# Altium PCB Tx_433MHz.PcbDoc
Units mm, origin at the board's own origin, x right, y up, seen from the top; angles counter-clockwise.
Board outline 100 x 50 mm, 4 copper layers (SIGNAL_1, SIGNAL_2, SIGNAL_3, SIGNAL_4), stack 1.58 mm thick; 34 components, 85 nets, 122 pads, 0 vias.
Unrouted connection lines stored in the file: 89.
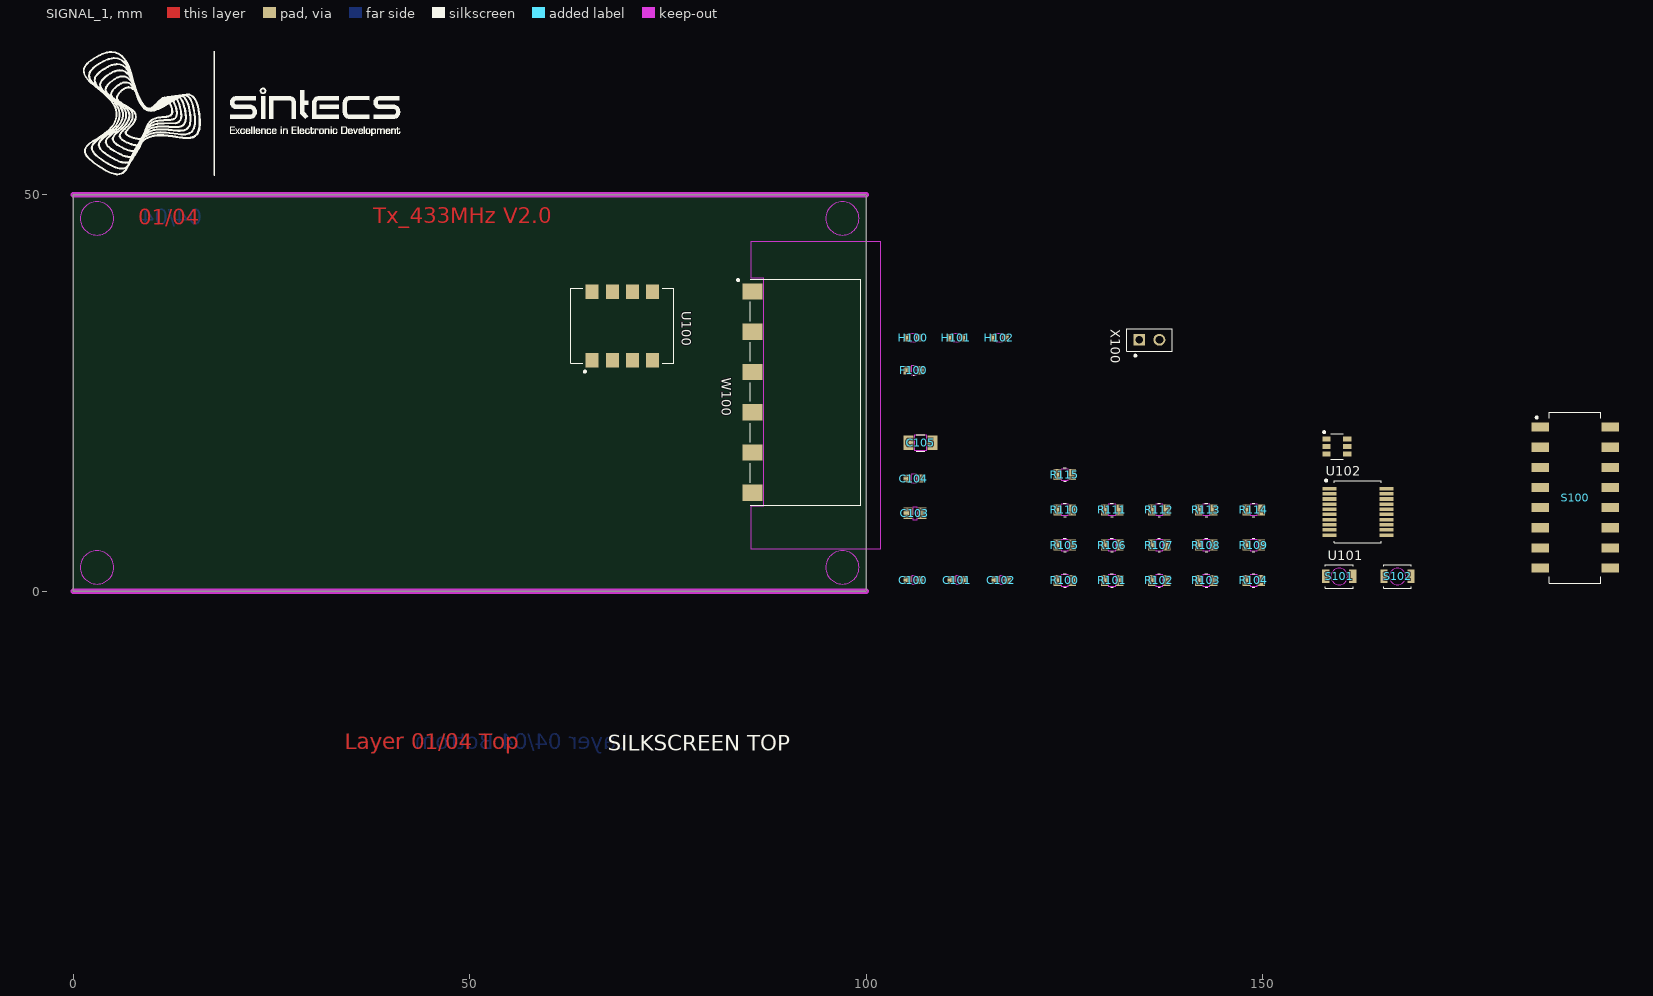
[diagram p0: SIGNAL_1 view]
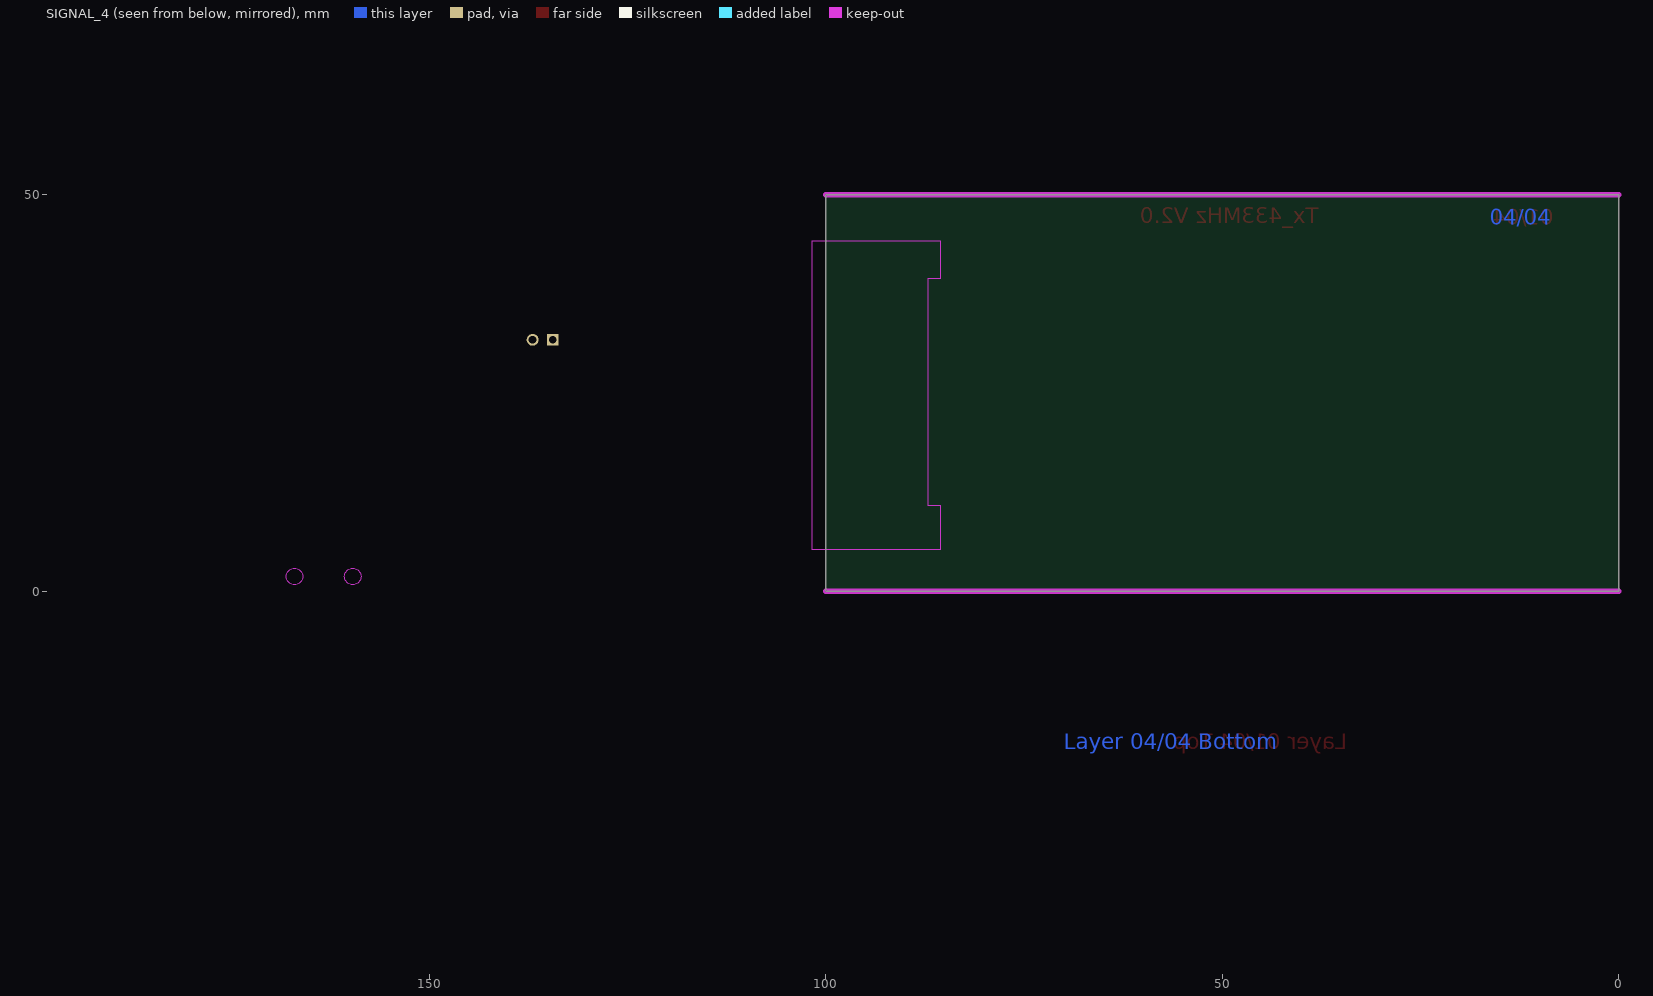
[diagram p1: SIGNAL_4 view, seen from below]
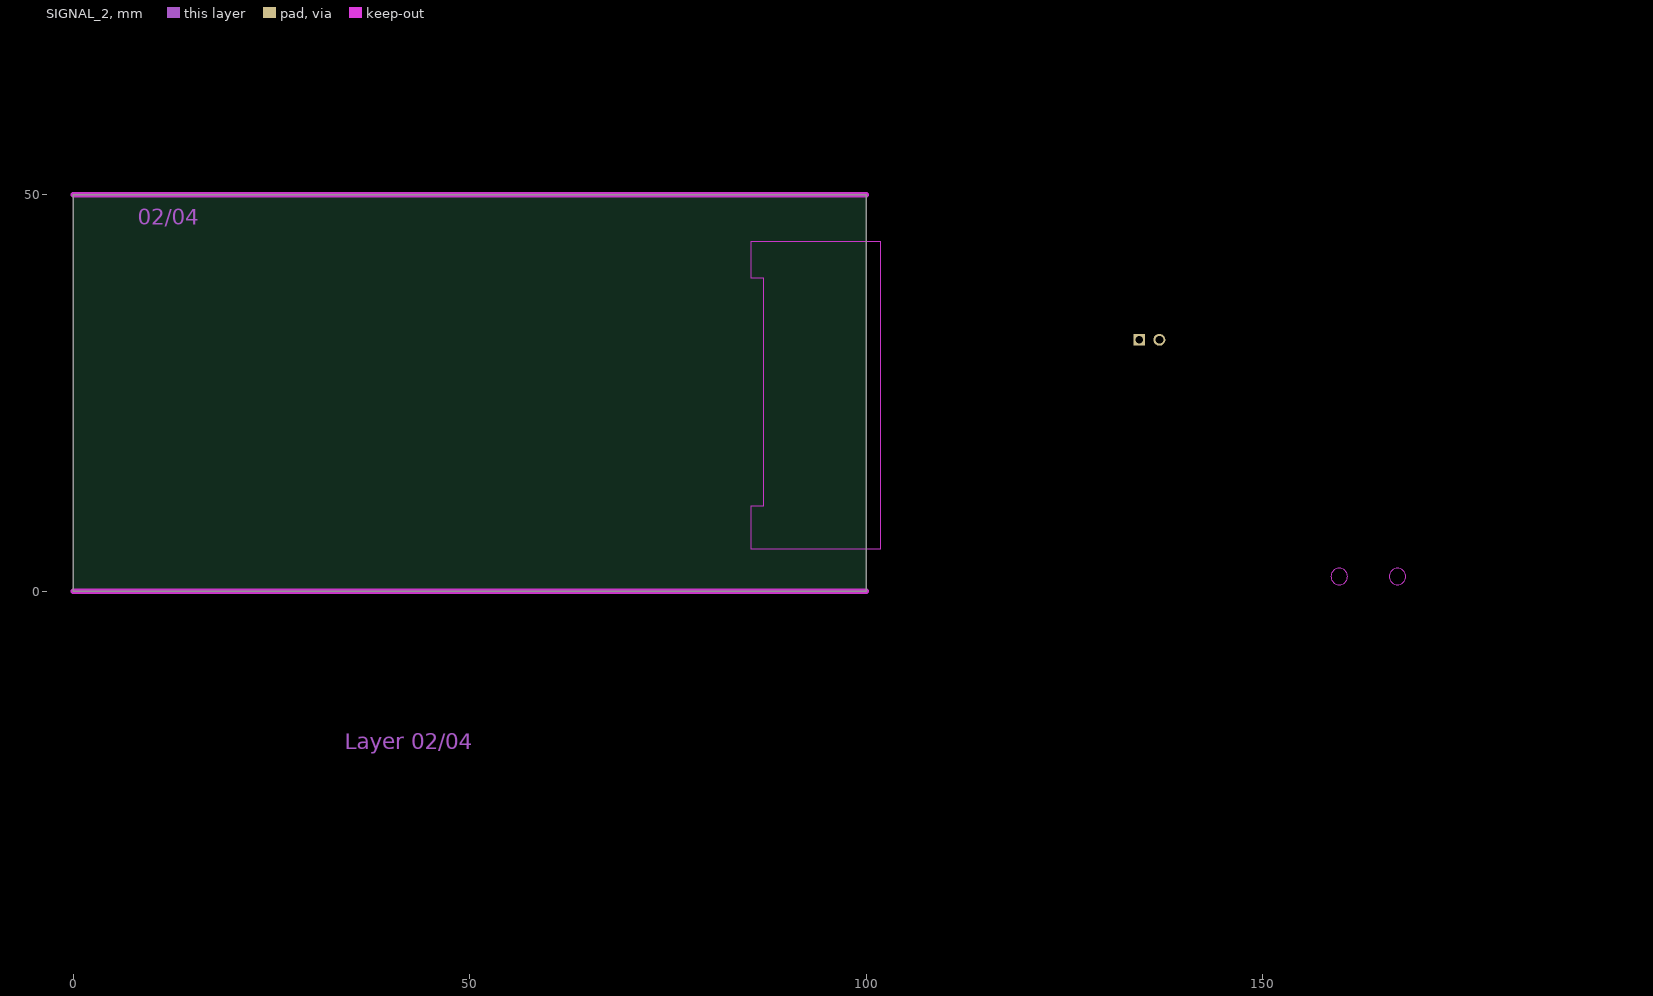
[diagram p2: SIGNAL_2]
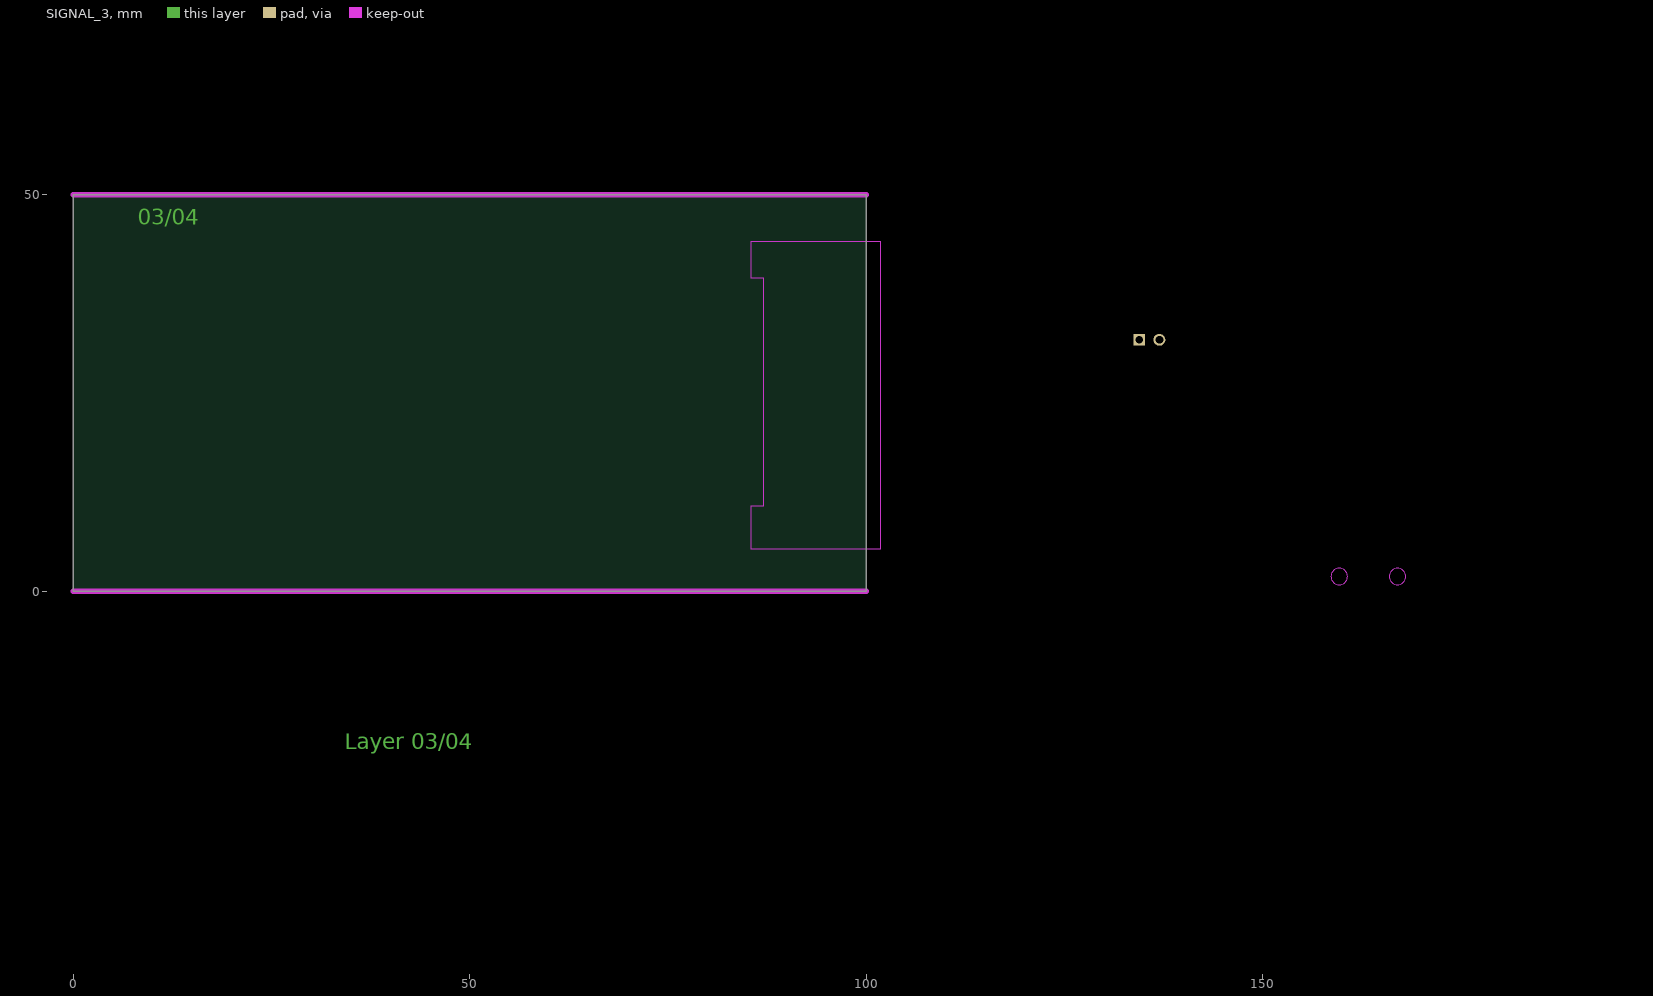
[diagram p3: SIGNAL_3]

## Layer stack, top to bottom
DIELECTRIC_1: solder mask 0.01, Dk 1
SIGNAL_1: signal copper 0.035
DIELECTRIC_3: prepreg 0.12, Dk 4.7
SIGNAL_2: signal copper 0.035
DIELECTRIC_5: prepreg 1.2, Dk 4.7
SIGNAL_3: signal copper 0.035
DIELECTRIC_7: prepreg 0.12, Dk 4.7
SIGNAL_4: signal copper 0.035
DIELECTRIC_9: solder mask 0.01, Dk 1

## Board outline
0,0 100,0 100,50 0,50

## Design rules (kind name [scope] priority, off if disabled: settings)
Clearance [All] p1: gap=0.15 ignorepadtopadclearanceinfootprint=FALSE
ComponentClearance [All] p1: gap=0.1 collisioncheckmode=3 verticalgap=0.254 showdistances=FALSE
DiffPairsRouting [All] p1: maxlimit=0.254 minlimit=0.254 mostfreqgap=0.254 toplayer_minwidth=0.15 toplayer_maxwidth=0.3 toplayer_prefwidth=0.15 midlayer1_minwidth=0.15 midlayer1_maxwidth=0.3 midlayer1_prefwidth=0.15 midlayer2_minwidth=0.15 midlayer2_maxwidth=0.3 midlayer2_prefwidth=0.15 bottomlayer_minwidth=0.15 bottomlayer_maxwidth=0.3 bottomlayer_prefwidth=0.15 maxuncoupledlength=12.7
PolygonConnect [All] p1: thpad.connectstyle=Relief thpad.reliefconductorwidth=0.15 thpad.reliefentries=4 thpad.polygonreliefangle="90 Angle" thpad.airgapwidth=0.15 smdpad.connectstyle=Relief smdpad.reliefconductorwidth=0.15 smdpad.reliefentries=4 smdpad.polygonreliefangle="90 Angle" smdpad.airgapwidth=0.15 via.connectstyle=Direct via.reliefconductorwidth=0.127 via.reliefentries=2 via.polygonreliefangle="90 Angle" via.airgapwidth=0.152
RoutingVias [All] p1: holewidth=0.3 width=0.7 viastyle="Through Hole" minholewidth=0.3 minwidth=0.7 maxholewidth=0.3 maxwidth=0.7
SolderMaskExpansion SolderMaskExpansion_Via [IsVia] p1: expansion=0.075 istentingtop=FALSE soldermaskfromhole=TRUE
SolderMaskExpansion [All] p2: expansion=0.1 istentingtop=FALSE
SupplyNets "Schematic Supply Nets_1" [InNet('3V3_TX')] p1: voltage=0.000
SupplyNets "Schematic Supply Nets" [InNet('GND_TX')] p2: voltage=0.000
UnRoutedNet [All] p1: checkbadconnections=TRUE
Width "Width for 50E_SE" [InNetClass('50R')] p1: maxlimit=0.2 minlimit=0.185 preferedwidth=0.2 toplayer_minwidth=0.2 bottomlayer_minwidth=0.2 impedanceprofiledriven=TRUE minimp=50.000000 maximp=50.000000 favimp=50.000000
Width [All] p2: maxlimit=1 minlimit=0.15 preferedwidth=0.2
27 further rules are at their usual default settings.

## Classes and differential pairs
net class 50R: $1N1841_TX

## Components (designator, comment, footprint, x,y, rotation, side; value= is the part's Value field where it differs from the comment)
C100 "C_0603_1608X90_GENERIC" CAPC1608X90N_0603_GENERIC 105.95,1.4 r0 top
C101 "C_0603_1608X90_GENERIC" CAPC1608X90N_0603_GENERIC 111.5,1.4 r0 top
C102 "C_0603_1608X90_GENERIC" CAPC1608X90N_0603_GENERIC 117.05,1.4 r0 top
C103 "C_0805_2012X150_GENERIC" CAPC2012X150N_0805_GENERIC 106.15,9.8 r0 top
C104 "CL10A226MP8NUNE" CAPC1608X105N 106,14.2 r0 top
C105 "C_1206_3216X190_GENERIC" CAPC3216X190N_1206_GENERIC 106.85,18.7 r0 top
F100 "0467XXXX" RESC1608X60N_0603_GENERIC 106,27.85 r0 top
H100 "KP-1608SGC" LEDC1608X110N 105.9,31.95 r0 top
H101 "KP-1608SGC" LEDC1608X110N 111.35,31.95 r0 top
H102 "KP-1608SGC" LEDC1608X110N 116.8,31.95 r0 top
R100 "R_0805_2012X60_GENERIC" RESC2012X60N_0805_GENERIC 125.05,1.35 r0 top
R101 "R_0805_2012X60_GENERIC" RESC2012X60N_0805_GENERIC 131,1.35 r0 top
R102 "R_0805_2012X60_GENERIC" RESC2012X60N_0805_GENERIC 136.95,1.35 r0 top
R103 "R_0805_2012X60_GENERIC" RESC2012X60N_0805_GENERIC 142.9,1.35 r0 top
R104 "R_0805_2012X60_GENERIC" RESC2012X60N_0805_GENERIC 148.85,1.35 r0 top
R105 "R_0805_2012X60_GENERIC" RESC2012X60N_0805_GENERIC 125.05,5.8 r0 top
R106 "R_0805_2012X60_GENERIC" RESC2012X60N_0805_GENERIC 131,5.8 r0 top
R107 "R_0805_2012X60_GENERIC" RESC2012X60N_0805_GENERIC 136.95,5.8 r0 top
R108 "R_0805_2012X60_GENERIC" RESC2012X60N_0805_GENERIC 142.9,5.8 r0 top
R109 "R_0805_2012X60_GENERIC" RESC2012X60N_0805_GENERIC 148.85,5.8 r0 top
R110 "R_0805_2012X60_GENERIC" RESC2012X60N_0805_GENERIC 125.05,10.25 r0 top
R111 "R_0805_2012X60_GENERIC" RESC2012X60N_0805_GENERIC 131,10.25 r0 top
R112 "R_0805_2012X60_GENERIC" RESC2012X60N_0805_GENERIC 136.95,10.25 r0 top
R113 "R_0805_2012X60_GENERIC" RESC2012X60N_0805_GENERIC 142.9,10.25 r0 top
R114 "R_0805_2012X60_GENERIC" RESC2012X60N_0805_GENERIC 148.85,10.25 r0 top
R115 "R_0805_2012X60_GENERIC" RESC2012X60N_0805_GENERIC 125.05,14.7 r0 top
S100 "418121270808" WE_418121270808 189.4,11.8 r0 top
S101 "B3U_1000P_B" OMRON_B3U_1000P_B 159.65,1.85 r0 top
S102 "B3U_1000P_B" OMRON_B3U_1000P_B 167,1.85 r0 top
U100 "TXM-433-LR" LINX_TXM-433-LR 69.25,33.45 r90 top
U101 "LICAL-ENC-MS001" SOP65P780X200-20N 162,10 r0 top
U102 "MAX8881EU" SOT95P280X100-6N 159.35,18.25 r0 top
W100 "ANT-433-SP" LINX_ANT-433-SP 85.65,25.1 r270 top
X100 "M20_9770242" HARWIN_M20_9770242 135.7,31.7 r0 top

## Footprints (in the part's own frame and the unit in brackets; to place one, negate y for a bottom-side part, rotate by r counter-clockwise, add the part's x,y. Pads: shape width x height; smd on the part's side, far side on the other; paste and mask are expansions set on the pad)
CAPC1608X90N_0603_GENERIC [mm]
  rrect1% 1x1 smd paste-2539.97 mask-0.513: 1(-0.75,0) 2(0.75,0)
  SIGNAL_1 keep-out region: -0.22,-0.55 0.22,-0.55 0.22,0.55 -0.22,0.55
  body extent -1.5,-0.75 1.5,0.75, height 0.9
CAPC1608X105N [mm]
  rrect1% 1x1.05 smd paste-2539.97 mask-0.538: 1(-0.8,0) 2(0.8,0)
  SIGNAL_1 keep-out region: -0.3,-0.525 0.3,-0.525 0.3,0.525 -0.3,0.525
  body extent -1.55,-0.8 1.55,0.8, height 1.05
CAPC2012X150N_0805_GENERIC [mm]
  rrect1% 1.15x1.45 smd paste-2539.97 mask-0.738: 1(-0.9,0) 2(0.9,0)
  SIGNAL_1 keep-out region: -0.28,-0.78 0.28,-0.78 0.28,0.78 -0.28,0.78
  body extent -1.72,-1.05 1.73,1.05, height 1.5
CAPC3216X190N_1206_GENERIC [mm]
  rrect1% 1.25x1.8 smd paste-2539.97 mask-0.913: 1(-1.5,0) 2(1.5,0)
  SIGNAL_1 keep-out region: -0.8,-0.95 0.8,-0.95 0.8,0.95 -0.8,0.95
  silkscreen extent -0.55,-1.05 0.55,1.05, body extent -2.4,-1.15 2.4,1.15, height 1.9
HARWIN_M20_9770242 [mm]
  rrect1% 1.5x1.5 hole 1 paste-2539.97 mask-0.763: 1(-1.27,0)
  round 1.5 hole 1 paste-2539.97 mask-0.763: 2(1.27,0)
  silkscreen extent -2.87,-2.13 2.86,1.42, body extent -2.97,-1.52 2.96,1.52, height 8.38
LEDC1608X110N [mm]
  rrect1% 0.8x0.95 smd paste-2539.97 mask-0.488: 1(-0.8,0) 2(0.8,0)
  SIGNAL_1 keep-out region: -0.375,-0.5 0.375,-0.5 0.375,0.5 -0.375,0.5
  body extent -1.45,-0.75 1.45,0.75, height 0.65
LINX_ANT-433-SP [mm]
  rrect1% 2.05x2.55 smd paste-2539.97 mask-1.288: 1(-12.7,0) 2(-7.62,0) 3(-2.54,0) 4(2.54,0) 5(7.62,0) 6(12.7,0)
  SIGNAL_1 keep-out region: 14.35,-0.15 14.35,1.4 -14.35,1.4 -14.35,-0.15 -19.03,-0.15 -19.03,16.13 19.83,16.13 19.83,-0.15
  SIGNAL_2 keep-out region: 14.35,-0.15 14.35,1.4 -14.35,1.4 -14.35,-0.15 -19.03,-0.15 -19.03,16.13 19.83,16.13 19.83,-0.15
  SIGNAL_3 keep-out region: 14.35,-0.15 14.35,1.4 -14.35,1.4 -14.35,-0.15 -19.03,-0.15 -19.03,16.13 19.83,16.13 19.83,-0.15
  SIGNAL_4 keep-out region: 14.35,-0.15 14.35,1.4 -14.35,1.4 -14.35,-0.15 -19.03,-0.15 -19.03,16.13 19.83,16.13 19.83,-0.15
  silkscreen extent -14.25,-1.93 14.24,13.67, body extent -14.34,-1.55 14.34,13.77, height 1.5
LINX_TXM-433-LR [mm]
  rrect1% 1.8x1.65 smd paste-2539.97 mask-0.913: 1(-4.318,3.81) 2(-4.318,1.27) 3(-4.318,-1.27) 4(-4.318,-3.81) 5(4.318,-3.81) 6(4.318,-1.27) 7(4.318,1.27) 8(4.318,3.81)
  silkscreen extent -5.89,-6.5 4.72,6.5, body extent -5.5,-6.75 5.5,6.7, height 3.3
OMRON_B3U_1000P_B [mm]
  rrect1% 0.9x1.7 smd paste-2539.97 mask-0.863: 1(-1.7,0) 2(1.7,0)
  round 0 hole 0.85 unplated paste-2539.97 mask+0.925: ""(0,0)
  SIGNAL_1 keep-out region: 1.05,0 0.97,0.402 0.742,0.742 0.402,0.97 0,1.05 0,1.05 -0.402,0.97 -0.742,0.742 -0.97,0.402 -1.05,0 -1.05,0 -0.97,-0.402 -0.742,-0.742 -0.402,-0.97 0,-1.05 0,-1.05 0.402,-0.97 0.742,-0.742 0.97,-0.402 1.05,0
  SIGNAL_2 keep-out region: 1.05,0 0.97,0.402 0.742,0.742 0.402,0.97 0,1.05 0,1.05 -0.402,0.97 -0.742,0.742 -0.97,0.402 -1.05,0 -1.05,0 -0.97,-0.402 -0.742,-0.742 -0.402,-0.97 0,-1.05 0,-1.05 0.402,-0.97 0.742,-0.742 0.97,-0.402 1.05,0
  SIGNAL_3 keep-out region: 1.05,0 0.97,0.402 0.742,0.742 0.402,0.97 0,1.05 0,1.05 -0.402,0.97 -0.742,0.742 -0.97,0.402 -1.05,0 -1.05,0 -0.97,-0.402 -0.742,-0.742 -0.402,-0.97 0,-1.05 0,-1.05 0.402,-0.97 0.742,-0.742 0.97,-0.402 1.05,0
  SIGNAL_4 keep-out region: 1.05,0 0.97,0.402 0.742,0.742 0.402,0.97 0,1.05 0,1.05 -0.402,0.97 -0.742,0.742 -0.97,0.402 -1.05,0 -1.05,0 -0.97,-0.402 -0.742,-0.742 -0.402,-0.97 0,-1.05 0,-1.05 0.402,-0.97 0.742,-0.742 0.97,-0.402 1.05,0
  silkscreen extent -1.75,-1.5 1.75,1.5, body extent -2.4,-1.6 2.4,1.6, height 1.75
RESC1608X60N_0603_GENERIC [mm]
  rrect1% 0.95x1.05 smd paste-2539.97 mask-0.538: 1(-0.8,0) 2(0.8,0)
  SIGNAL_1 keep-out region: -0.3,-0.55 0.3,-0.55 0.3,0.55 -0.3,0.55
  silkscreen extent -0.08,-0.65 0.08,0.65, body extent -1.55,-0.8 1.55,0.8, height 0.6
RESC2012X60N_0805_GENERIC [mm]
  rrect1% 0.95x1.4 smd paste-2539.97 mask-0.713: 1(-0.95,0) 2(0.95,0)
  SIGNAL_1 keep-out region: -0.45,-0.7 0.45,-0.7 0.45,0.7 -0.45,0.7
  silkscreen extent -0.2,-0.85 0.15,0.85, body extent -1.7,-0.95 1.7,0.95, height 0.6
SOP65P780X200-20N [mm]
  rrect1% 1.75x0.45 smd paste-2539.97 mask-0.888: 1(-3.6,2.925) 2(-3.6,2.275) 3(-3.6,1.625) 4(-3.6,0.975) 5(-3.6,0.325) 6(-3.6,-0.325) 7(-3.6,-0.975) 8(-3.6,-1.625) 9(-3.6,-2.275) 10(-3.6,-2.925) 11(3.6,-2.925) 12(3.6,-2.275) 13(3.6,-1.625) 14(3.6,-0.975) 15(3.6,-0.325) 16(3.6,0.325) 17(3.6,0.975) 18(3.6,1.625) 19(3.6,2.275) 20(3.6,2.925)
  silkscreen extent -4.13,-3.9 2.95,4.08, body extent -4.75,-4 4.75,4, height 2
SOT95P280X100-6N [mm]
  rrect1% 1.05x0.6 smd paste-2539.97 mask-0.538: 1(-1.3,0.95) 2(-1.3,0) 3(-1.3,-0.95) 4(1.3,-0.95) 5(1.3,0) 6(1.3,0.95)
  silkscreen extent -1.73,-1.6 0.8,1.92, body extent -2.1,-1.7 2.1,1.7, height 1
WE_418121270808 [mm]
  rrect1% 2.2x1.15 smd paste-2539.97 mask-1.113: 1(-4.4,8.89) 2(-4.4,6.35) 3(-4.4,3.81) 4(-4.4,1.27) 5(-4.4,-1.27) 6(-4.4,-3.81) 7(-4.4,-6.35) 8(-4.4,-8.89) 9(4.4,-8.89) 10(4.4,-6.35) 11(4.4,-3.81) 12(4.4,-1.27) 13(4.4,1.27) 14(4.4,3.81) 15(4.4,6.35) 16(4.4,8.89)
  silkscreen extent -4.97,-10.78 3.25,10.78, body extent -5.75,-10.9 5.75,10.9, height 4.32

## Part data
C100 C101 C102: "100nF"
C103: "1uF"
C104: "4.7uF"
C105: "10uF"
F100: "500mA"
R100 R101 R102: "120R"
R103 R104 R105 R106 R107 R108 R109 R110 R112 R115: "100K"
R111 R113 R114: "1K"
U100: "LR Series Transmitter, Low Voltage, Low Power", Manufacturer="Linx Technologies", Max Temp=85, Min Temp=-40, Package=custom
W100: "433MHz 50 Ohm Antenna module", Manufacturer="Linx Technologies", Max Temp=130, Min Temp=-40, Package=custom

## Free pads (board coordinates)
  round 0.025 smd far side paste-2539.97 mask-127: ""(7.05,43.55) ""(80.8,-44.8)
  round 0 hole 2.2 unplated paste-2539.97 mask+1.6: ""(66.6,58.9) ""(76.6,58.9) ""(86.6,58.9) ""(96.6,58.9)

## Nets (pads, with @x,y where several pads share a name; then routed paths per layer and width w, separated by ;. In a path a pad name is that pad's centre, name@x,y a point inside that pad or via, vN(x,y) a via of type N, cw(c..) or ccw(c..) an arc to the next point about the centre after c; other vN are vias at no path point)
3V3_RX: 
3V3_TX: C100.1 C101.1 C102.1 C104.1 C105.1 R100.1 R111.2 S101.2 S102.2 U100.4 U100.7 U101.15 U101.16 U102.3 U102.4
$1N313_TX: C103.1 F100.1 X100.1
$1N314_TX: F100.2 U102.1 U102.5
$1N437_RX: 
$1N720_TX: U100.2 U101.9
$1N743_TX: R107.1 S100.16 U101.1
$1N745_TX: R108.1 S100.15 U101.2
$1N747_TX: R109.1 S100.14 U101.13
$1N749_TX: R110.1 S100.13 U101.14
$1N751_TX: R106.2 S100.12 U101.17
$1N753_TX: R105.2 S100.11 U101.18
$1N755_TX: R104.2 S100.10 U101.19
$1N757_TX: R103.2 S100.9 U101.20
$1N759_TX: R111.1 S100.1 S100.2 S100.3 S100.4 S100.5 S100.6 S100.7 S100.8
$1N795_RX: 
$1N1120_TX: H101.2 R102.1
$1N1214_TX: H101.1 U100.8 U101.8
$1N1223_TX: H102.2 R101.1
$1N1291_RX: 
$1N1295_RX: 
$1N1297_RX: 
$1N1299_RX: 
$1N1301_RX: 
$1N1303_RX: 
$1N1305_RX: 
$1N1307_RX: 
$1N1309_RX: 
$1N1311_RX: 
$1N1313_RX: 
$1N1315_RX: 
$1N1317_RX: 
$1N1317_TX: H102.1 U101.10
$1N1321_RX: 
$1N1323_RX: 
$1N1544_TX: R113.2 U101.12
$1N1569_TX: R112.2 R113.1 S101.1
$1N1574_RX: 
$1N1625_RX: 
$1N1658_TX: R114.1 R115.2 S102.1
$1N1708_TX: R114.2 U101.11
$1N1841_TX: U100.5 W100.1
$1N2058_RX: 
$1N2060_RX: 
$1N2062_RX: 
$1N2064_RX: 
$1N2066_RX: 
$1N2068_RX: 
$1N2070_RX: 
$1N2072_RX: 
$1N2073_RX: 
$1N2074_RX: 
$1N2075_RX: 
$1N2076_RX: 
$1N2077_RX: 
$1N2078_RX: 
$1N2081_RX: 
$1N2082_RX: 
$1N2083_RX: 
$1N2084_RX: 
$1N2085_RX: 
$1N2086_RX: 
$1N2087_RX: 
$1N2088_RX: 
$1N2089_RX: 
$1N2090_RX: 
$1N2091_RX: 
$1N2092_RX: 
$1N2093_RX: 
$1N2094_RX: 
$1N2316_TX: H100.1 R100.2 U102.6
$1N2995_RX: 
$1N3048_RX: 
$1N3132_RX: 
$1N3379_RX: 
$1N3381_RX: 
$1N3506_RX: 
$1N3765_RX: 
$1N3866_RX: 
$1N4024_RX: 
DEC_MODE_IND_RX: 
GND: H100.2
GND_RX: 
GND_TX: C100.2 C101.2 C102.2 C103.2 C104.2 C105.2 R101.2 R102.2 R103.1 R104.1 R105.1 R106.1 R107.2 R108.2 R109.2 R110.2 R112.1 R115.1 U100.1 U100.3 U100.6 U101.3 U101.4 U101.5 U101.6 U101.7 U102.2 W100.2 W100.3 W100.4 W100.5 W100.6 X100.2
RX_DATA_RX: 
pads on no net: S101. S102.

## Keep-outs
SIGNAL_1:
  region: 5.1,3 ccw(c3,3) 3,5.1 ccw(c3,3) 0.9,3 ccw(c3,3) 3,0.9 ccw(c3,3)
  region: 99.1,3 ccw(c97,3) 97,5.1 ccw(c97,3) 94.9,3 ccw(c97,3) 97,0.9 ccw(c97,3)
  region: 99.1,47 ccw(c97,47) 97,49.1 ccw(c97,47) 94.9,47 ccw(c97,47) 97,44.9 ccw(c97,47)
  region: 5.1,47 ccw(c3,47) 3,49.1 ccw(c3,47) 0.9,47 ccw(c3,47) 3,44.9 ccw(c3,47)
Keep-Out Layer:
  lines w0.7: 0,0 100,0 ; 0,50 100,50

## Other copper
SIGNAL_1:
  pour cut-out: 5.1,3 ccw(c3,3) 3,5.1 ccw(c3,3) 0.9,3 ccw(c3,3) 3,0.9 ccw(c3,3)
  pour cut-out: 99.1,3 ccw(c97,3) 97,5.1 ccw(c97,3) 94.9,3 ccw(c97,3) 97,0.9 ccw(c97,3)
  pour cut-out: 99.1,47 ccw(c97,47) 97,49.1 ccw(c97,47) 94.9,47 ccw(c97,47) 97,44.9 ccw(c97,47)
  pour cut-out: 5.1,47 ccw(c3,47) 3,49.1 ccw(c3,47) 0.9,47 ccw(c3,47) 3,44.9 ccw(c3,47)
  text "Tx_433MHz V2.0" at 37.866,46.425 h2
  text "01/04" at 8.186,46.175 h2
  text "Layer 01/04 Top" at 34.224,-19.965 h2
SIGNAL_2:
  text "02/04" at 8.156,46.175 h2
  text "Layer 02/04" at 34.224,-19.965 h2
SIGNAL_3:
  text "03/04" at 8.156,46.175 h2
  text "Layer 03/04" at 34.224,-19.965 h2
SIGNAL_4:
  text "04/04" at 16.264,46.175 h2
  text "Layer 04/04 Bottom" at 69.973,-19.965 h2

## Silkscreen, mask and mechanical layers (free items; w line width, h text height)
Top Overlay:
  drawing of 94 lines, arcs and shapes, not listed
  text "SILKSCREEN TOP" at 67.397,-20.135 h2
DIELECTRIC_1:
  text "SOLDERMASK TOP" at 34.234,-19.905 h2
DIELECTRIC_9:
  text "SOLDERMASK BOTTOM" at 34.244,-19.905 h2
Top Assembly:
  text "Assembly Drawing Top" at 34.504,-20.19 h2
Default User Layer:
  lines w0.025: 1,1 1,49 ; 1,1 85,1 ; 1,1 1,49 ; 1,1 85,1 ; 1,49 85,49 ; 1,49 85,49 ; 85,1 85,49 ; 85,1 85,49
VSCORE_DETAIL:
  lines w0.1: 0,0 100,0
  text "VSCORE DETAIL" at 34.234,-19.905 h2
Panel Dimension:
  text "Panel Drawing" at 34.764,-20.195 h2
Single Board Dimensions:
  the board outline again, w0.05
  text "Single Board Dimensions" at 34.234,-19.905 h2
TitleBlock_Mirrored:
  drawing of 102 lines, arcs and shapes, not listed
  text "PROJECT:" at 76.949,-10.749 h0.76
  text "TX & RX 433MHZ UT Scintilla Workshop" at 69.887,-12.451 h2
  text "DRAWN BY:" at 76.949,-14.559 h0.76
  text "Lesley Snijder/Henk Mengerink" at 70.091,-16.181 h2
  text "LAYER:" at 76.949,-18.369 h0.76
  text "DATE:" at 17.513,-22.179 h0.76
  text "REV:" at 27.419,-22.179 h0.76
  text "DWG NO:" at 76.949,-22.179 h0.76
  text "30 Apr2021" at 13.449,-23.941 h2
  text "2.0" at 24.117,-23.941 h2
  text "THE INFORMATION HEREIN IS PROPRIETARY TO YOUR DESIGN COMPANY" at 112.609,-24.528 h0.64
TittleBlock:
  drawing of 102 lines, arcs and shapes, not listed
  text "PROJECT:" at 27.789,-10.769 h0.76
  text "TX & RX 433MHZ UT Scintilla Workshop" at 34.647,-12.431 h2
  text "DRAWN BY:" at 27.789,-14.579 h0.76
  text "Lesley Snijder/Henk Mengerink" at 34.647,-16.201 h2
  text "LAYER:" at 27.789,-18.389 h0.76
  text "DWG NO:" at 27.789,-22.199 h0.76
  text "REV:" at 77.319,-22.199 h0.76
  text "DATE:" at 87.225,-22.199 h0.76
  text "2.0" at 80.621,-23.961 h2
  text "30 Apr 2021" at 91.289,-23.961 h2
  text "THE INFORMATION HEREIN IS PROPRIETARY TO YOUR DESIGN COMPANY" at -7.871,-24.548 h0.64
Drill Drawing:
  lines w0.15: -22.95,-95.95 134.55,-95.95 ; -22.95,-89.95 134.55,-89.95 ; -22.95,-112.45 -22.95,-80.95 134.55,-80.95 134.55,-112.45 -22.95,-112.45
  text "E" at 3,46 h2
  text "E" at 97,46 h2
  text "A" at 66.42,41.24 h2
  text "A" at 71.68,41.24 h2
  text "A" at 43.09,40.65 h2
  text "A" at 56.5,40.65 h2
  text "A" at 31,38.55 h2
  text "A" at 6.98,38.49 h2
  text "D" at 43.1,38 h2
  text "D" at 56.5,38 h2
  text "A" at 49.85,37.74 h2
  text "A" at 38.54,36.13 h2
  text "A" at 18.66,35.93 h2
  text "A" at 78.64,35 h2
  text "A" at 82.3,34.67 h2
  text "A" at 41.17,34.05 h2
  text "A" at 54.57,34.05 h2
  text "A" at 83.76,31.72 h2
  text "A" at 78.92,30.83 h2
  text "A" at 58.77,29.72 h2
  text "A" at 51.12,28.4 h2
  text "A" at 54.98,28.4 h2
  text "A" at 65.43,26.73 h2
  text "A" at 70.52,26.73 h2
  text "A" at 73.05,26.73 h2
  text "A" at 6.89,26.65 h2
  text "A" at 83.76,26.64 h2
  text "A" at 51.12,25.85 h2
  text "A" at 54.98,25.85 h2
  text "A" at 68.6,25.09 h2
  text "A" at 30.84,24.25 h2
  text "A" at 56.5,24.18 h2
  text "A" at 51.12,23.3 h2
  text "A" at 79.23,23.15 h2
  text "A" at 83.76,21.56 h2
  text "A" at 51.12,20.8 h2
  text "A" at 79.23,20.6 h2
  text "A" at 65.64,20.55 h2
  text "A" at 68.69,19.57 h2
  text "A" at 54.9,19.55 h2
  text "A" at 18.54,18.46 h2
  text "A" at 57.4,18.46 h2
  text "A" at 65.65,18.25 h2
  text "A" at 51.12,18.2 h2
  text "A" at 69.01,17.28 h2
  text "A" at 83.76,16.48 h2
  text "A" at 69.01,15.96 h2
  text "A" at 51.12,15.7 h2
  text "A" at 70.96,14.65 h2
  text "A" at 79.05,14.65 h2
  text "A" at 69.7,14.39 h2
  text "A" at 51.12,13.15 h2
  text "A" at 6.78,12.23 h2
  text "C" at 60.23,11.67 h2
  text "A" at 83.76,11.4 h2
  text "A" at 51.12,10.6 h2
  text "A" at 64.84,10.6 h2
  text "A" at 30.67,9.95 h2
  text "C" at 60.23,9.13 h2
  text "A" at 64.85,9.1 h2
  text "A" at 78.85,7.44 h2
  text "E" at 3,2 h2
  text "E" at 97,2 h2
  text "E" at 3,-4 h2
  text "E" at 97,-4 h2
  text "A" at 4.63,-8.14 h2
  text "A" at 29.48,-8.79 h2
  text "A" at 66.43,-9.29 h2
  text "C" at 45.53,-9.32 h2
  text "C" at 48.07,-9.32 h2
  text "A" at 53.83,-9.3 h2
  text "B" at 3.055,-11.42 h2
  text "B" at 18.295,-11.42 h2
  text "A" at 47.53,-12 h2
  text "A" at 34.53,-12.33 h2
  text "A" at 50.78,-13.9 h2
  text "A" at 46.55,-13.94 h2
  text "B" at 3.055,-13.96 h2
  text "B" at 18.295,-13.96 h2
  text "A" at 46.56,-15.09 h2
  text "A" at 77.44,-15.31 h2
  text "A" at 82.12,-15.31 h2
  text "A" at 50.78,-15.8 h2
  text "A" at 74.65,-15.84 h2
  text "A" at 34.53,-16.13 h2
  text "B" at 3.055,-16.5 h2
  text "B" at 18.295,-16.5 h2
  text "A" at 39.37,-17.08 h2
  text "A" at 42.26,-17.4 h2
  text "A" at 50.79,-18.23 h2
  text "A" at 83.11,-18.38 h2
  text "A" at 39.37,-18.98 h2
  text "B" at 3.055,-19.04 h2
  text "B" at 18.295,-19.04 h2
  text "A" at 51.5,-20.8 h2
  text "A" at 78.52,-21.54 h2
  text "B" at 3.055,-21.58 h2
  text "B" at 18.295,-21.58 h2
  text "A" at 37.98,-21.68 h2
  text "A" at 26.55,-23.3 h2
  text "A" at 83.11,-23.46 h2
  text "A" at 30.1,-23.53 h2
  text "A" at 51.5,-23.79 h2
  text "A" at 25.5,-24 h2
  text "A" at 14.55,-25.06 h2
  text "C" at 42,-26.22 h2
  text "A" at 30.78,-26.91 h2
  text "A" at 37.97,-26.9 h2
  text "A" at 51.12,-27.75 h2
  text "B" at 2.905,-28.22 h2
  text "B" at 18.145,-28.22 h2
  text "A" at 83.11,-28.54 h2
  text "C" at 42,-28.76 h2
  text "A" at 34.53,-30.11 h2
  text "B" at 2.905,-30.76 h2
  text "B" at 18.145,-30.76 h2
  text "C" at 42,-31.3 h2
  text "A" at 48.38,-31.44 h2
  text "B" at 2.905,-33.3 h2
  text "B" at 18.145,-33.3 h2
  text "A" at 48.38,-33.34 h2
  text "A" at 83.11,-33.62 h2
  text "C" at 42,-33.84 h2
  text "A" at 34.53,-33.92 h2
  text "A" at 63.03,-34.18 h2
  text "A" at 39.39,-34.85 h2
  text "A" at 60.27,-35.46 h2
  text "B" at 2.905,-35.84 h2
  text "B" at 18.145,-35.84 h2
  text "A" at 78.41,-35.96 h2
  text "A" at 66.43,-36.15 h2
  text "C" at 42,-36.38 h2
  text "A" at 39.37,-36.76 h2
  text "A" at 60.24,-37.08 h2
  text "A" at 49.35,-37.1 h2
  text "A" at 51.85,-38.27 h2
  text "B" at 2.905,-38.38 h2
  text "B" at 18.145,-38.38 h2
  text "A" at 63.25,-38.41 h2
  text "A" at 83.11,-38.7 h2
  text "C" at 42,-38.92 h2
  text "A" at 63.39,-39.37 h2
  text "A" at 39.19,-40.16 h2
  text "A" at 63.39,-40.69 h2
  text "A" at 66.49,-41.12 h2
  text "A" at 58.79,-41.27 h2
  text "A" at 26,-41.3 h2
  text "A" at 30.05,-41.3 h2
  text "C" at 42,-41.46 h2
  text "A" at 37.1,-42.86 h2
  text "A" at 52.5,-43.2 h2
  text "D" at 55.15,-43.2 h2
  text "A" at 13.66,-43.25 h2
  text "C" at 42,-44 h2
  text "A" at 30.94,-44.5 h2
  text "E" at 3,-48 h2
  text "E" at 97,-48 h2
  text "Through Holes" at 47.75,-84.7 h1.5
  text "All Drills (unless specified) +/- 0.1000 (MM)" at 25.675,-87.7 h1.5
  text "Symbol" at -19.208,-93.7 h1.5
  text "Diameter" at 1.834,-93.7 h1.5
  text "Tolerance" at 29.561,-93.7 h1.5
  text "Plated" at 52.798,-93.7 h1.5
  text "HoleName" at 85.805,-93.7 h1.5
  text "Quantity" at 120.337,-93.7 h1.5
  text "A" at -15.45,-98.2 h1.5
  text "0.3000" at 3.379,-98.2 h1.5
  text "+/- 0.1000" at 29.132,-98.2 h1.5
  text "Yes" at 55.01,-98.2 h1.5
  text "Rnd 0.30 +/-Tol 0.10" at 77.714,-98.2 h1.5
  text "114" at 124.046,-98.2 h1.5
  text "B" at -15.45,-101.2 h1.5
  text "0.9000" at 3.379,-101.2 h1.5
  text "+/- 0.1000" at 29.132,-101.2 h1.5
  text "Yes" at 55.01,-101.2 h1.5
  text "Rnd 0.90 +/-Tol 0.10" at 77.714,-101.2 h1.5
  text "20" at 124.766,-101.2 h1.5
  text "C" at -15.45,-104.2 h1.5
  text "1.0000" at 3.402,-104.2 h1.5
  text "+/- 0.1000" at 29.132,-104.2 h1.5
  text "Yes" at 55.01,-104.2 h1.5
  text "Rnd 1.00 +/-Tol 0.10" at 77.74,-104.2 h1.5
  text "12" at 124.78,-104.2 h1.5
  text "D" at -15.45,-107.2 h1.5
  text "0.8500" at 3.385,-107.2 h1.5
  text "+/- 0.1000" at 29.132,-107.2 h1.5
  text "No" at 55.767,-107.2 h1.5
  text "Rnd 0.85 +/-Tol 0.10 Non-Plated" at 69.797,-107.2 h1.5
  text "3" at 125.55,-107.2 h1.5
  text "E" at -15.45,-110.2 h1.5
  text "2.2000" at 3.379,-110.2 h1.5
  text "+/- 0.1000" at 29.132,-110.2 h1.5
  text "No" at 55.767,-110.2 h1.5
  text "Rnd 2.20 +/-Tol 0.10 Non-Plated" at 69.79,-110.2 h1.5
  text "8" at 125.55,-110.2 h1.5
